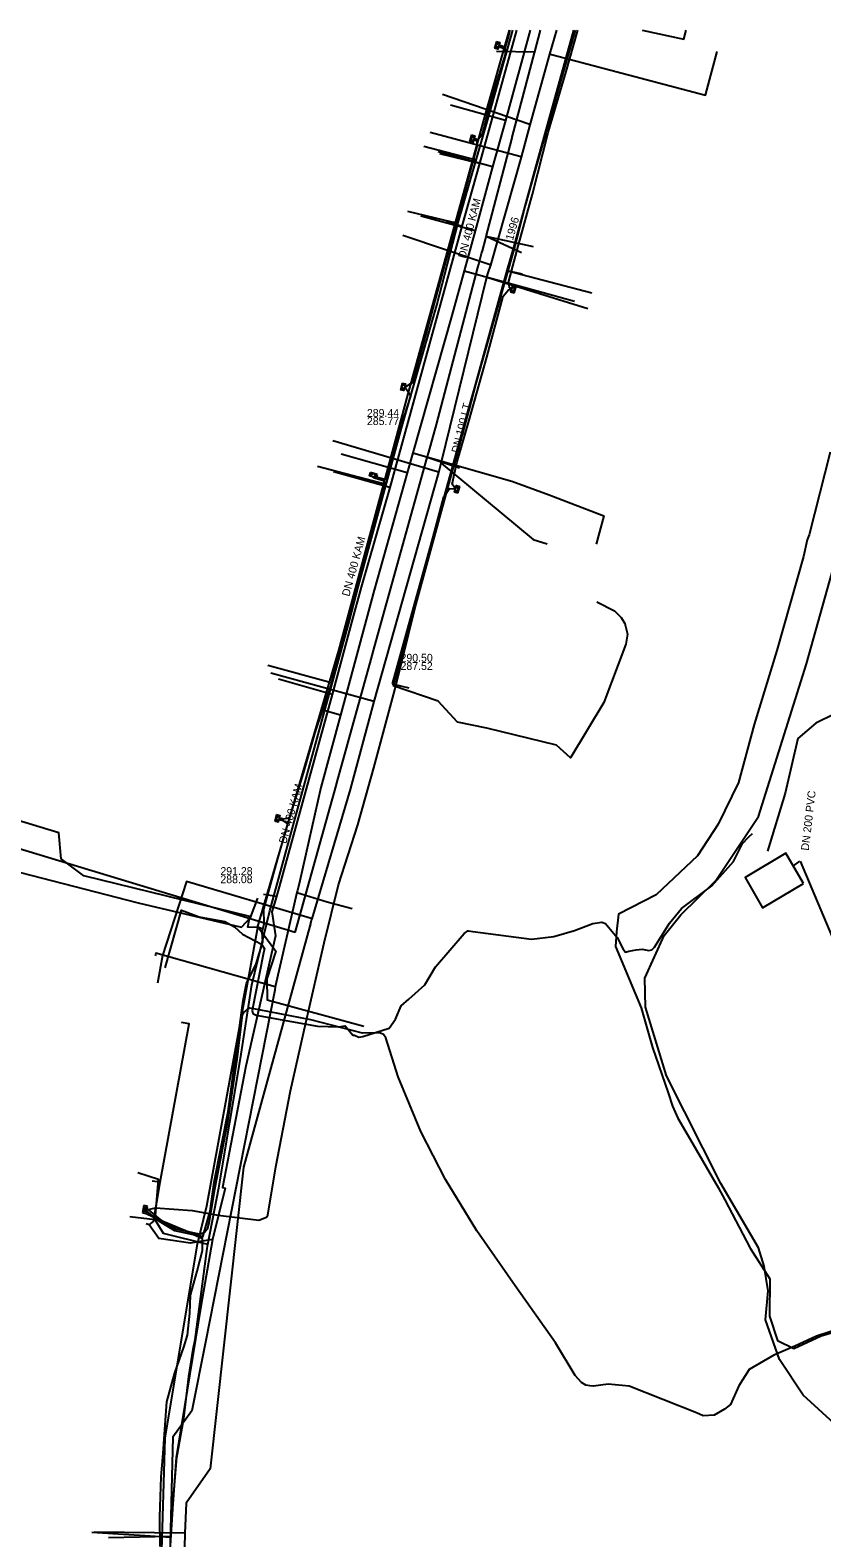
# Model space of a CAD drawing. Extents: x -600391 to -599491, y -1160176 to -1159402.
# Drawn here: x -599914.1 to -599833.6, y -1159555.1 to -1159401.8 of the extents above; entities that cross this region are included whole.
import ezdxf

# ---------------------------------------------------------------- set-up
doc = ezdxf.new("R2010")
doc.units = 0
for name, color, linetype in [('28', 7, 'Continuous'), ('31', 7, 'Continuous'), ('CETIN_linie', 7, 'Continuous'), ('FASTER_linie', 7, 'Continuous'), ('T-mobile_linie', 7, 'Continuous'), ('UPC_ok_linie', 7, 'Continuous'), ('Vrstva 1', 7, 'Continuous'), ('Vrstva 12', 7, 'Continuous'), ('Vrstva 13', 7, 'Continuous'), ('Vrstva 15', 7, 'Continuous'), ('Vrstva 16', 7, 'Continuous'), ('Vrstva 3', 7, 'Continuous'), ('Vrstva 42', 7, 'Continuous'), ('Vrstva 43', 7, 'Continuous'), ('Vrstva 55', 7, 'Continuous'), ('Vrstva 58', 7, 'Continuous'), ('Vrstva 8', 7, 'Continuous'), ('Vrstva 9', 7, 'Continuous')]:
    doc.layers.add(name, color=color, linetype=linetype)

# ---------------------------------------------------------------- blocks, each defined once
blk = doc.blocks.new('NN630')
at = {"layer": '31'}
for points in [[(0, -0.7), (-0.7, 0)], [(-0.7, -0.7), (-0.7, 0), (0.7, 0), (0.7, -0.7)], [(-0.7, -0.7), (0.7, -0.7)], [(0, -0.7), (0.7, 0)]]:
    blk.add_lwpolyline(points, dxfattribs=at)
blk = doc.blocks.new('NN620')
at = {"layer": '28'}
for points in [[(0.75, 0), (-0.75, 0)], [(-0.75, 0), (-0.75, -0.75)], [(0.75, -0.75), (0.75, 0)], [(-0.75, -0.75), (0.75, -0.75)], [(0.37, -0.18), (-0.38, -0.18)], [(-0.38, -0.18), (-0.38, -0.56)], [(-0.38, -0.56), (0.37, -0.56)], [(0.32, -0.23), (-0.33, -0.23)], [(-0.33, -0.23), (-0.33, -0.51)], [(-0.33, -0.51), (0.32, -0.51)], [(0.27, -0.27), (-0.28, -0.27)], [(-0.28, -0.27), (-0.28, -0.46)], [(-0.28, -0.46), (0.27, -0.46)], [(0.23, -0.32), (-0.23, -0.32)], [(-0.23, -0.32), (-0.23, -0.42)], [(-0.23, -0.42), (0.23, -0.42)], [(-0.19, -0.37), (0.19, -0.37)], [(0.23, -0.42), (0.23, -0.32)], [(0.27, -0.46), (0.27, -0.27)], [(0.32, -0.51), (0.32, -0.23)], [(0.37, -0.56), (0.37, -0.18)]]:
    blk.add_lwpolyline(points, dxfattribs=at)

msp = doc.modelspace()

# ---------------------------------------------------------------- linework, layer by layer
at = {"layer": 'CETIN_linie'}
msp.add_line((-599889.89, -1159466.32), (-599883.31, -1159468.12), dxfattribs=at)
for points in [[(-599858.65, -1159401.77), (-599862.75, -1159416.1), (-599863.72, -1159419.61), (-599864.08, -1159421.06), (-599864.78, -1159423.73), (-599868.77, -1159437.79), (-599869.41, -1159440.26), (-599875.83, -1159463.7), (-599877.15, -1159468.44)], [(-599870.53, -1159421.31), (-599867.52, -1159410.85), (-599864.99, -1159401.77)], [(-599868.71, -1159415), (-599868.71, -1159415), (-599874.02, -1159413.6)], [(-599875.68, -1159420.18), (-599871.18, -1159421.27), (-599870.53, -1159421.31)], [(-599895.99, -1159525.23), (-599894.88, -1159519.47), (-599892.68, -1159506.31), (-599891.53, -1159498.82), (-599889.7, -1159491.32), (-599887.2, -1159482.25), (-599881.57, -1159461.78), (-599880.66, -1159458.27), (-599876.28, -1159442.25), (-599875.48, -1159439.4), (-599872.69, -1159429.72), (-599870.53, -1159421.31)], [(-599856.95, -1159428.51), (-599865.5, -1159426.29)], [(-599877.84, -1159447.95), (-599877.84, -1159447.95), (-599884.84, -1159446.15)], [(-599856.43, -1159459.9), (-599854.63, -1159460.82), (-599853.96, -1159461.47), (-599853.58, -1159462.1), (-599853.58, -1159462.1), (-599853.3, -1159463.19), (-599853.48, -1159464.21), (-599855.73, -1159470.13), (-599859.11, -1159475.76), (-599860.52, -1159474.48), (-599867.62, -1159472.75), (-599870.6, -1159472.13), (-599872.56, -1159469.98), (-599877.15, -1159468.44)], [(-599895.99, -1159525.23), (-599900.51, -1159524.12), (-599901.34, -1159522.72), (-599901, -1159518.63), (-599903.12, -1159517.96)], [(-599901.34, -1159522.72), (-599903.93, -1159522.42)], [(-599900.27, -1159564.22), (-599900.06, -1159560.12), (-599899.45, -1159550.52), (-599899.14, -1159546.88), (-599898.42, -1159542.91), (-599897.93, -1159538.66), (-599897.48, -1159535.86), (-599897.29, -1159534.88), (-599896.04, -1159525.63), (-599895.99, -1159525.23)], [(-599907.79, -1159554.47), (-599899.73, -1159554.99)]]:
    msp.add_lwpolyline(points, dxfattribs=at)
at = {"layer": 'FASTER_linie'}
msp.add_lwpolyline([(-599806.85, -1159471.45), (-599808.57, -1159469.66), (-599812.78, -1159465.92), (-599815.61, -1159464.23), (-599817.92, -1159464.25), (-599834.16, -1159472.24), (-599835.99, -1159473.78), (-599837.27, -1159479.34), (-599839.09, -1159485.23)], dxfattribs=at)
at = {"layer": 'T-mobile_linie'}
msp.add_line((-599877.56, -1159503.23), (-599876.92, -1159502.31), dxfattribs=at)
for points in [[(-599840.97, -1159483.79), (-599840.61, -1159483.46)], [(-599876.92, -1159502.31), (-599876.32, -1159500.98), (-599875.54, -1159500.28), (-599873.94, -1159498.82), (-599872.84, -1159497.01), (-599869.94, -1159493.62), (-599869.56, -1159493.36), (-599869.49, -1159493.35), (-599869.03, -1159493.42), (-599863.09, -1159494.2), (-599860.82, -1159493.92), (-599858.71, -1159493.3), (-599856.83, -1159492.61), (-599855.92, -1159492.46), (-599855.54, -1159492.59), (-599854.35, -1159494.03), (-599853.74, -1159495.22), (-599853.52, -1159495.52), (-599853.18, -1159495.42), (-599852.45, -1159495.27), (-599851.81, -1159495.21), (-599851.14, -1159495.36), (-599850.85, -1159495.29), (-599850.56, -1159494.99), (-599849.05, -1159492.58), (-599847.81, -1159491.07), (-599844.75, -1159488.76), (-599842.54, -1159486.31), (-599841.63, -1159484.45), (-599840.97, -1159483.79)], [(-599900.32, -1159497.1), (-599898.66, -1159491.23), (-599896.88, -1159491.92), (-599894.26, -1159492.41), (-599893.29, -1159492.94), (-599892.47, -1159493.69), (-599890.53, -1159494.7), (-599890.23, -1159495.16), (-599890.32, -1159495.57), (-599891.48, -1159501.43), (-599891.4, -1159501.76)], [(-599891.4, -1159501.76), (-599891.07, -1159501.92), (-599884.84, -1159503.04)], [(-599884.84, -1159503.04), (-599882.7, -1159503.11), (-599882.03, -1159503.01), (-599881.23, -1159503.96), (-599881.06, -1159503.96), (-599880.63, -1159504.14), (-599880.22, -1159504.1)], [(-599880.22, -1159504.1), (-599877.56, -1159503.23)]]:
    msp.add_lwpolyline(points, dxfattribs=at)
at = {"layer": 'UPC_ok_linie'}
for p, q in [((-599864.59, -1159401.77), (-599868.38, -1159415.31)), ((-599868.38, -1159415.31), (-599872.39, -1159414.34)), ((-599868.38, -1159415.31), (-599870.16, -1159421.7)), ((-599870.16, -1159421.7), (-599877.49, -1159448.26)), ((-599870.16, -1159421.7), (-599871.75, -1159421.28)), ((-599865.59, -1159426.19), (-599864.03, -1159426.54)), ((-599877.49, -1159448.26), (-599883.2, -1159446.67)), ((-599883.34, -1159469.33), (-599888.79, -1159467.74)), ((-599883.34, -1159469.33), (-599888.99, -1159489.86)), ((-599877.25, -1159468.24), (-599875.54, -1159468.65)), ((-599888.99, -1159489.86), (-599890.33, -1159489.65)), ((-599901.96, -1159523.23), (-599902.25, -1159523.14)), ((-599899.77, -1159554.93), (-599906.09, -1159555.05)), ((-599899.77, -1159554.93), (-599900.03, -1159560.67))]:
    msp.add_line(p, q, dxfattribs=at)
for points in [[(-599858.8, -1159401.77), (-599862.77, -1159416.08), (-599864.84, -1159423.63), (-599865.59, -1159426.19)], [(-599865.59, -1159426.19), (-599868.83, -1159437.96), (-599869.53, -1159440.35), (-599877.25, -1159468.24)], [(-599877.49, -1159448.26), (-599880.39, -1159458.41), (-599881.39, -1159462.01), (-599883.34, -1159469.33)], [(-599948.2, -1159477.53), (-599945.05, -1159478.55), (-599931.87, -1159482.13), (-599930.22, -1159482.12), (-599917.35, -1159486.62), (-599915.03, -1159487.41), (-599903.07, -1159490.48), (-599892.55, -1159492.96), (-599891.65, -1159491.98), (-599890.92, -1159490.01)], [(-599888.99, -1159489.86), (-599889.47, -1159491.42), (-599889.1, -1159493.86), (-599892.11, -1159507.12), (-599894.51, -1159519.45), (-599894.21, -1159519.52), (-599895.53, -1159524.72)], [(-599900.84, -1159518.9), (-599897.88, -1159502.81), (-599898.68, -1159502.68)], [(-599901.96, -1159523.23), (-599901.5, -1159522.91), (-599900.84, -1159518.9)], [(-599900.84, -1159518.9), (-599901.65, -1159518.79)], [(-599895.53, -1159524.72), (-599897.75, -1159525.1), (-599900.96, -1159524.61), (-599901.96, -1159523.23)], [(-599895.53, -1159524.72), (-599896.71, -1159531.54), (-599899.21, -1159546.89), (-599899.77, -1159554.93)]]:
    msp.add_lwpolyline(points, dxfattribs=at)
at = {"layer": 'Vrstva 1'}
for p, q in [((-599835.82, -1159486.27), (-599836.48, -1159486.72)), ((-599829.66, -1159500.68), (-599835.73, -1159486.27))]:
    msp.add_line(p, q, dxfattribs=at)
at = {"layer": 'Vrstva 13'}
for p, q in [((-599867.61, -1159426.9), (-599857.36, -1159430.08)), ((-599885.56, -1159492.69), (-599885.61, -1159492.86)), ((-599898.33, -1159554.58), (-599907.54, -1159554.47))]:
    msp.add_line(p, q, dxfattribs=at)
for points in [[(-599885.56, -1159492.69), (-599885.4, -1159492.14), (-599885.39, -1159492.11), (-599881.48, -1159478.98), (-599879.09, -1159470.02), (-599872.49, -1159446.73), (-599872.26, -1159445.79), (-599867.61, -1159426.9), (-599867.49, -1159426.45), (-599867.21, -1159425.66), (-599864.11, -1159414.69), (-599863.2, -1159411.4), (-599861.2, -1159404.21), (-599860.51, -1159401.77)], [(-599861.2, -1159404.21), (-599861.04, -1159404.25), (-599845.37, -1159408.39), (-599844.19, -1159403.94)], [(-599863.2, -1159411.4), (-599863.35, -1159411.33), (-599872.14, -1159408.32)], [(-599864.11, -1159414.69), (-599864.27, -1159414.63), (-599873.37, -1159412.16)], [(-599867.21, -1159425.66), (-599867.38, -1159425.6), (-599876.16, -1159422.66)], [(-599872.49, -1159446.73), (-599872.65, -1159446.69), (-599883.27, -1159443.54)], [(-599872.26, -1159445.79), (-599862.92, -1159453.56), (-599861.5, -1159454)], [(-599879.09, -1159470.02), (-599879.22, -1159469.98), (-599889.57, -1159467.16)], [(-599885.39, -1159492.11), (-599885.57, -1159492.05), (-599898.17, -1159488.34), (-599900.61, -1159495.84), (-599901.12, -1159498.67)], [(-599885.61, -1159492.86), (-599892.35, -1159517.38), (-599895.75, -1159548.06), (-599898.18, -1159551.55), (-599898.33, -1159554.58), (-599898.49, -1159562.01), (-599898.87, -1159579.54), (-599898.94, -1159585.2), (-599899.01, -1159592.25), (-599899.24, -1159607.34), (-599899.31, -1159619.59), (-599899.75, -1159646.69), (-599898.89, -1159648.24)]]:
    msp.add_lwpolyline(points, dxfattribs=at)
at = {"layer": 'Vrstva 16'}
for points in [[(-599863.21, -1159401.77), (-599865.73, -1159410.94), (-599867.03, -1159415.66), (-599868.82, -1159422.18), (-599869.93, -1159426.23), (-599871.18, -1159430.77), (-599875.13, -1159444.74), (-599875.71, -1159446.79), (-599879.09, -1159458.72), (-599882.51, -1159471.4), (-599884.49, -1159478.76), (-599886.65, -1159488.25)], [(-599851.81, -1159401.77), (-599847.59, -1159402.68), (-599847.35, -1159401.77)], [(-599865.73, -1159410.94), (-599871.3, -1159409.41)], [(-599867.03, -1159415.66), (-599872.57, -1159414.14)], [(-599868.82, -1159422.18), (-599874.32, -1159420.67)], [(-599869.93, -1159426.23), (-599863.48, -1159428), (-599858.71, -1159429.31)], [(-599875.71, -1159446.79), (-599882.43, -1159444.88)], [(-599875.13, -1159444.74), (-599868.77, -1159446.57), (-599865.07, -1159447.63), (-599861.29, -1159449.01), (-599855.71, -1159451.14), (-599856.49, -1159454.04)], [(-599882.51, -1159471.4), (-599884.31, -1159470.92)], [(-599886.87, -1159489.23), (-599886.93, -1159489.46), (-599889.14, -1159499.05), (-599889.19, -1159499.39), (-599896.23, -1159535.16), (-599897.6, -1159542.16)], [(-599886.93, -1159489.46), (-599883.85, -1159490.39), (-599881.32, -1159491.06)], [(-599886.65, -1159488.25), (-599886.87, -1159489.23)], [(-599889.14, -1159499.05), (-599901.29, -1159495.62), (-599901.32, -1159495.79), (-599901.34, -1159495.89)], [(-599897.6, -1159542.16), (-599899.54, -1159544.83), (-599899.82, -1159555.55), (-599899.92, -1159559.24), (-599899.98, -1159561.55), (-599899.99, -1159561.7), (-599900.12, -1159566.78), (-599900.49, -1159584.59), (-599900.75, -1159597.19), (-599900.98, -1159608.08), (-599901.23, -1159620.16), (-599901.42, -1159629.09), (-599901.47, -1159632.81), (-599901.63, -1159644.36), (-599901.67, -1159646.88), (-599901.86, -1159662.98), (-599924.82, -1159689), (-599969.78, -1159714.48)]]:
    msp.add_lwpolyline(points, dxfattribs=at)
at = {"layer": 'Vrstva 3'}
msp.add_lwpolyline([(-599835.41, -1159488.52), (-599837.23, -1159485.46), (-599841.34, -1159487.91), (-599839.58, -1159491.01)], close=True, dxfattribs=at)
at = {"layer": 'Vrstva 42'}
for points in [[(-599902.18, -1159521.59), (-599900.79, -1159522.73), (-599899.25, -1159523.65), (-599897.38, -1159524.05), (-599896.49, -1159524.47), (-599895.75, -1159521.86), (-599895.34, -1159518.91), (-599893.93, -1159511.72), (-599892.39, -1159500.42), (-599892.04, -1159498.69), (-599891.09, -1159496.71), (-599890.41, -1159494.46), (-599890.48, -1159493.45), (-599890.26, -1159492.62), (-599890.29, -1159491.13), (-599888.88, -1159485.99), (-599887.84, -1159482.48), (-599888.3, -1159482.15), (-599888.57, -1159482.1), (-599888.75, -1159481.96), (-599888.53, -1159481.9), (-599888.25, -1159481.95), (-599887.65, -1159481.82), (-599886.27, -1159477.3), (-599885.07, -1159473.17), (-599883.48, -1159468.48), (-599881.97, -1159462.43), (-599880.52, -1159457.27), (-599878.67, -1159450.24), (-599877.96, -1159447.97), (-599878.01, -1159447.62), (-599879.05, -1159447.33), (-599879.22, -1159447.18), (-599879, -1159447.14), (-599877.97, -1159447.42), (-599877.61, -1159446.83), (-599876.34, -1159442.02), (-599875.35, -1159438.99), (-599875.97, -1159438.08), (-599875.18, -1159437.6), (-599873.74, -1159432.53), (-599871.98, -1159426.05), (-599870.12, -1159419.24), (-599868.59, -1159413.6), (-599868.59, -1159413.06), (-599868.79, -1159413), (-599868.95, -1159412.85), (-599868.73, -1159412.81), (-599868.51, -1159412.87), (-599868.04, -1159412.2), (-599867.01, -1159408.37), (-599865.71, -1159404.23), (-599865.73, -1159403.71), (-599866.24, -1159403.52), (-599866.39, -1159403.36), (-599866.17, -1159403.33), (-599865.71, -1159403.5), (-599865.5, -1159402.69), (-599865.24, -1159401.77)], [(-599902.18, -1159521.72), (-599901.32, -1159521.5), (-599897.57, -1159521.78), (-599894.94, -1159522.24), (-599890.8, -1159522.75), (-599890.03, -1159522.47), (-599889.88, -1159522.24), (-599889.07, -1159517.34), (-599887.59, -1159509.62), (-599886.04, -1159502.7), (-599884.15, -1159494.55), (-599882.69, -1159488.68), (-599880.73, -1159482.55), (-599879.12, -1159476.77), (-599876.97, -1159468.85), (-599875.6, -1159463.2), (-599873.54, -1159455.09), (-599872, -1159449.22), (-599871.43, -1159448.36), (-599870.8, -1159448.42), (-599871.14, -1159447.94), (-599870.67, -1159445.76), (-599869.41, -1159441.43), (-599867.62, -1159435.02), (-599865.96, -1159428.8), (-599865.41, -1159428.17), (-599865.08, -1159428.08), (-599865.33, -1159427.97), (-599865.38, -1159427.3), (-599864.43, -1159423.74), (-599862.96, -1159418.43), (-599861.37, -1159412.18), (-599859.54, -1159405.97), (-599858.35, -1159401.77)], [(-599832.7, -1159444.66), (-599834.85, -1159453.07), (-599835.06, -1159453.59), (-599835.41, -1159455.3), (-599838.12, -1159464.84), (-599840.45, -1159472.36), (-599842.03, -1159478.25), (-599844.08, -1159482.51), (-599846.21, -1159485.71), (-599850.41, -1159489.67), (-599854.22, -1159491.65), (-599854.44, -1159493.45), (-599854.55, -1159494.94), (-599851.92, -1159501.17), (-599850.79, -1159505.22), (-599849.17, -1159509.81), (-599848.74, -1159511.17), (-599848.2, -1159512.39), (-599846.9, -1159514.59), (-599844.09, -1159519.45), (-599843.42, -1159520.71), (-599840.86, -1159525.6), (-599838.85, -1159528.73), (-599838.87, -1159532.52), (-599838.06, -1159534.98), (-599836.41, -1159535.81), (-599833.61, -1159534.52), (-599832.25, -1159534.11)], [(-599831.78, -1159533.82), (-599834.09, -1159534.55), (-599836.31, -1159535.56), (-599838.45, -1159536.5), (-599840.96, -1159537.95), (-599842, -1159539.59), (-599842.85, -1159541.49), (-599843.46, -1159541.99), (-599844.5, -1159542.6), (-599845.63, -1159542.66), (-599846.31, -1159542.36), (-599853.15, -1159539.65), (-599855.29, -1159539.43), (-599856.78, -1159539.65), (-599857.15, -1159539.59), (-599857.56, -1159539.53), (-599857.99, -1159539.27), (-599858.63, -1159538.54), (-599860.63, -1159535.23), (-599864.73, -1159529.45), (-599868.62, -1159523.86), (-599871.81, -1159518.62), (-599874.32, -1159513.76), (-599876.63, -1159508.19), (-599877.9, -1159504.21), (-599878.11, -1159503.9), (-599878.42, -1159503.75), (-599878.9, -1159503.73), (-599880.26, -1159503.76), (-599885.5, -1159502.39), (-599890.77, -1159501.36), (-599891.73, -1159501.22), (-599892.01, -1159501.37), (-599892.34, -1159501.62), (-599892.48, -1159501.9), (-599893.03, -1159506.42), (-599894.03, -1159512.97), (-599895.3, -1159519.64), (-599895.84, -1159522.91), (-599896.06, -1159523.68), (-599896.34, -1159524), (-599896.63, -1159524.15), (-599896.81, -1159524.19), (-599897.86, -1159524.02), (-599901.04, -1159522.69), (-599902.27, -1159522.11)], [(-599900.84, -1159555.93), (-599900.87, -1159552.94), (-599900.73, -1159548.85), (-599900.52, -1159546.5), (-599900.42, -1159544.98), (-599900.17, -1159541.23), (-599899.35, -1159538.3), (-599898.43, -1159535.69), (-599898.07, -1159534.44), (-599897.81, -1159532.21), (-599897.75, -1159530.37), (-599897.06, -1159527.96), (-599896.52, -1159525.86), (-599896.53, -1159524.67), (-599897.44, -1159524.25), (-599899.33, -1159523.83), (-599900.91, -1159522.89), (-599902.2, -1159521.83)]]:
    msp.add_lwpolyline(points, dxfattribs=at)
at = {"layer": 'Vrstva 55'}
for points in [[(-599865.36, -1159401.77), (-599867.82, -1159410.45), (-599875.65, -1159438.73), (-599882.71, -1159464.83), (-599890.96, -1159493.01)], [(-599890.94, -1159493), (-599891.91, -1159492.97), (-599891.73, -1159491.88), (-599908.6, -1159487.75), (-599910.89, -1159486.03), (-599911.14, -1159483.38), (-599936.4, -1159475.73)], [(-599890.94, -1159493.03), (-599896.12, -1159521.34), (-599897.1, -1159525.36), (-599900.35, -1159544.92), (-599900.72, -1159557.47), (-599901.66, -1159588.88), (-599902.37, -1159619.84), (-599902.51, -1159647.36), (-599899.26, -1159651.62)], [(-599890.5, -1159493.15), (-599890.86, -1159492.98), (-599889.08, -1159495.42), (-599890, -1159498.22), (-599889.94, -1159500.36), (-599880.12, -1159503.03)]]:
    msp.add_lwpolyline(points, dxfattribs=at)
at = {"layer": 'Vrstva 58'}
msp.add_lwpolyline([(-599829.18, -1159546.29), (-599835.44, -1159540.56), (-599837.85, -1159536.93), (-599839.28, -1159532.91), (-599839.02, -1159529.95), (-599839.43, -1159527.44), (-599839.98, -1159525.57), (-599843.83, -1159519.04), (-599849.34, -1159508.1), (-599851.49, -1159501.12), (-599851.55, -1159498.14), (-599849.58, -1159493.81), (-599847.88, -1159491.7), (-599844.33, -1159488.22), (-599839.99, -1159481.72), (-599835.13, -1159466.19), (-599830.29, -1159449)], dxfattribs=at)
at = {"layer": 'Vrstva 9'}
for p, q in [((-599866.64, -1159403.91), (-599862.73, -1159403.97)), ((-599864.08, -1159424.41), (-599867.67, -1159422.74)), ((-599862.87, -1159423.79), (-599867.67, -1159422.74)), ((-599870.41, -1159446.3), (-599873.68, -1159445.22)), ((-599887.12, -1159493.5), (-599942.92, -1159476.63))]:
    msp.add_line(p, q, dxfattribs=at)
for points in [[(-599872.73, -1159441.87), (-599868.53, -1159425.9), (-599868.44, -1159425.57), (-599868.15, -1159424.49), (-599868.07, -1159424.21), (-599867.76, -1159423.04), (-599867.67, -1159422.74), (-599865.09, -1159412.86), (-599865.04, -1159412.68), (-599865.04, -1159412.66), (-599862.76, -1159404.07), (-599862.73, -1159403.98), (-599862.73, -1159403.97), (-599862.15, -1159401.77)], [(-599879.38, -1159465.71), (-599879.03, -1159464.46), (-599873.68, -1159445.22), (-599873.52, -1159444.66), (-599872.73, -1159441.87)], [(-599887.12, -1159493.5), (-599882.91, -1159478.48), (-599882.89, -1159478.43), (-599879.38, -1159465.71)]]:
    msp.add_lwpolyline(points, dxfattribs=at)

# ---------------------------------------------------------------- block references
at = {"layer": 'Vrstva 43'}
for name, p, xscale, yscale, rotation in [('NN630', (-599866.39, -1159403.36), 0.5, 0.5, -106.00000000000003), ('NN630', (-599868.95, -1159412.85), 0.5, 0.5, -106.00000000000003), ('NN630', (-599865.08, -1159428.08), 0.5, 0.5000000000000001, 75), ('NN630', (-599875.97, -1159438.08), 0.5, 0.5000000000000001, -105), ('NN630', (-599879.22, -1159447.18), 0.5000000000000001, 0.5, 163), ('NN630', (-599870.8, -1159448.42), 0.5, 0.5000000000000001, 75), ('NN630', (-599888.75, -1159481.96), 0.5, 0.5000000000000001, -105), ('NN620', (-599902.18, -1159521.72), 0.49999999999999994, 0.5, -100)]:
    msp.add_blockref(name, p, dxfattribs=dict(at, xscale=xscale, yscale=yscale, rotation=rotation))

# ---------------------------------------------------------------- texts
at = {"layer": 'Vrstva 12'}
for rotation, p in [(75.2867, (-599869.79, -1159425.03)), (74.5991, (-599881.61, -1159459.4)), (74.4272, (-599888.02, -1159484.54))]:
    msp.add_text('DN 400 KAM', height=0.8, rotation=rotation, dxfattribs=at).set_placement(p)
for s, p in [('289.44', (-599879.81, -1159441.09)), ('285.77', (-599879.81, -1159441.92)), ('290.50', (-599876.39, -1159465.98)), ('287.52', (-599876.39, -1159466.82)), ('291.28', (-599894.71, -1159487.67)), ('288.08', (-599894.71, -1159488.5))]:
    msp.add_text(s, height=0.8, dxfattribs=at).set_placement(p)
at = {"layer": 'Vrstva 15'}
for s, rotation, p in [('1996', 74.198, (-599864.97, -1159423.2)), ('DN 100 LT', 76.1461, (-599870.46, -1159444.82))]:
    msp.add_text(s, height=0.8, rotation=rotation, dxfattribs=at).set_placement(p)
at = {"layer": 'Vrstva 8'}
msp.add_text('DN 200 PVC', height=0.8, rotation=83.2369, dxfattribs=at).set_placement((-599834.89, -1159485.22))

doc.saveas('drawing.dxf')
